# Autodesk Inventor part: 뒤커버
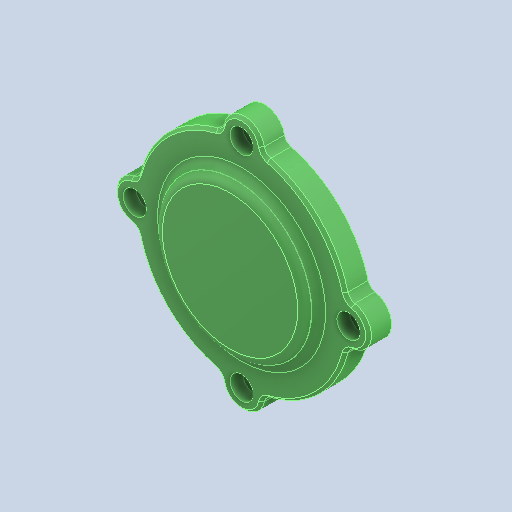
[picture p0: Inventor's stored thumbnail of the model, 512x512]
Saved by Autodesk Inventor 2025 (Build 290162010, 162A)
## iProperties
Created: 2024-08
Part Number: 뒤커버
Material: 알루미늄 6061
Document SubType Name: Modeling
Designer: 학생
Density: 2.71 g/cm^3
Appearance: 기본값
Company: 한국ATC센터
Author: jhkim
Sending System: Autodesk Inventor 2025
Preprocessor: ST-DEVELOPER v20
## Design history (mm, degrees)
feature "솔리드1"
node "솔리드2"
